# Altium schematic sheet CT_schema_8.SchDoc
size 370 x 335 mm
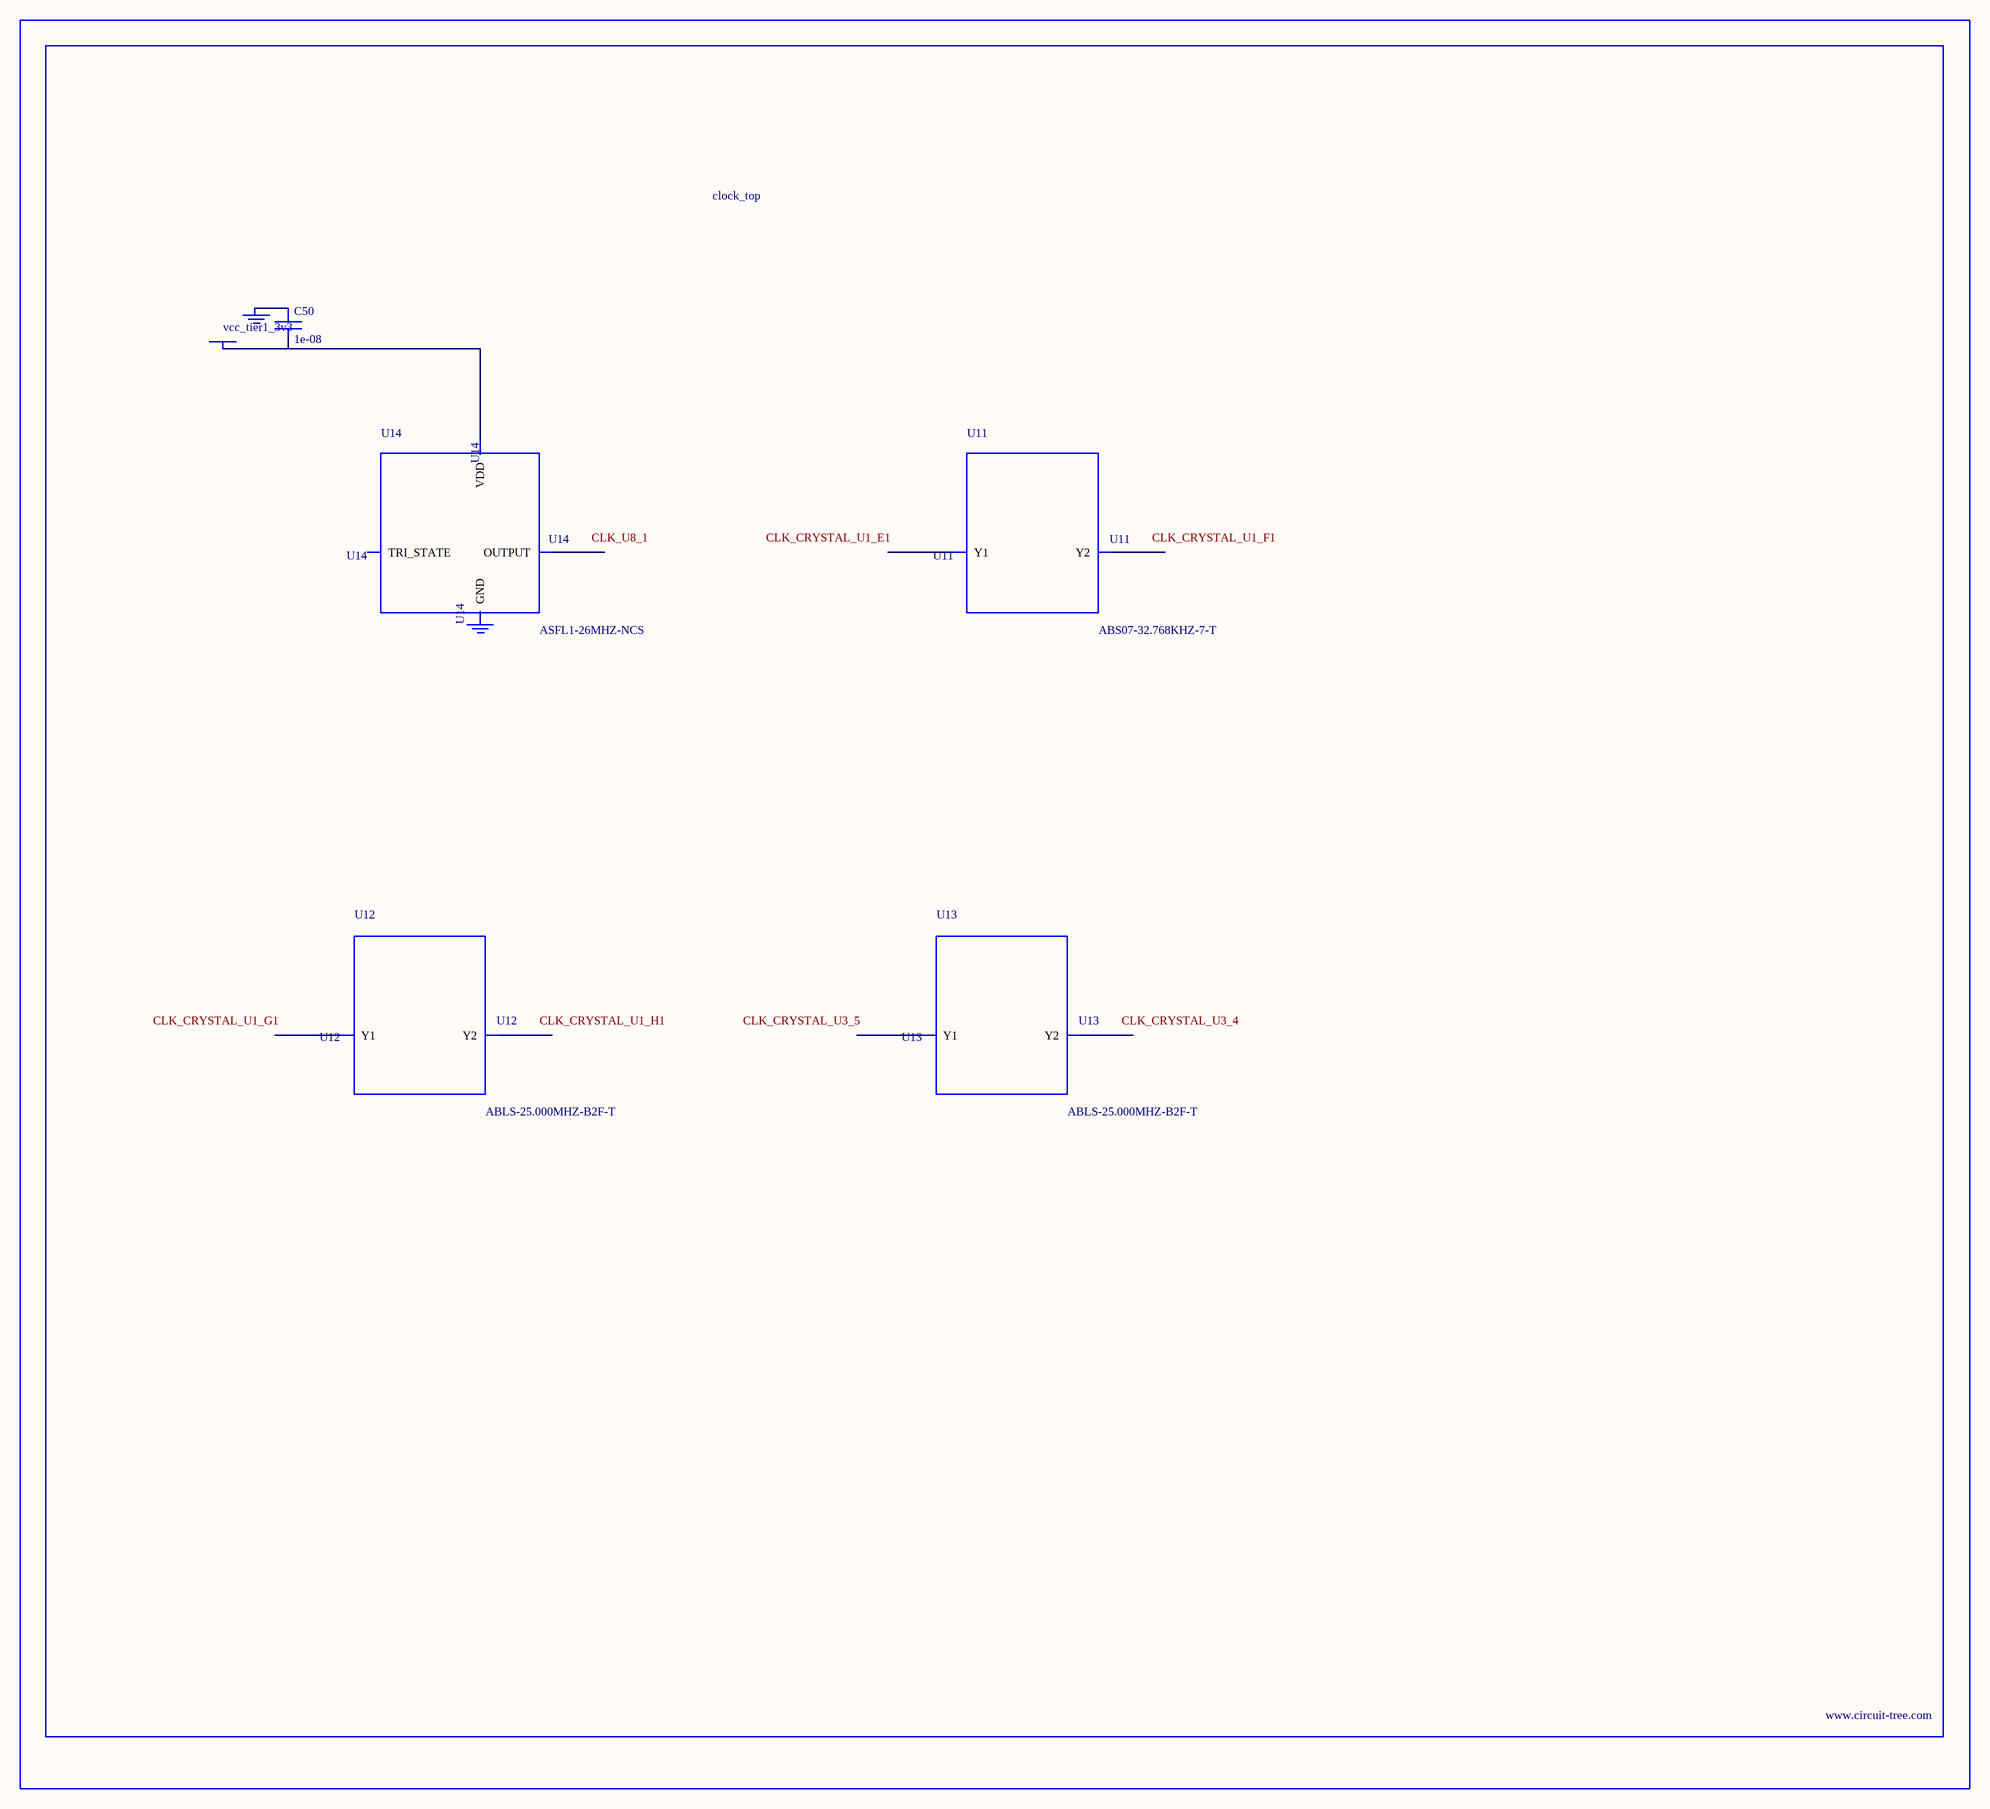
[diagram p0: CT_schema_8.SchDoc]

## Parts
BORDER7  (no value)
C50  1e-08  [C0402]
GND_INSTANCE_7_0  (no value)
GND_INSTANCE_7_1  (no value)
POWER_INSTANCE_7_0  vcc_tier1_3v3
U11  ABS07-32.768KHZ-7-T  [ABS07-32.768KHZ-7-T]
U12  ABLS-25.000MHZ-B2F-T  [ABLS-25.000MHZ-B2F-T]
U13  ABLS-25.000MHZ-B2F-T  [ABLS-25.000MHZ-B2F-T]
U14  ASFL1-26MHZ-NCS  [ASFL1]

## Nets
NetC50_1: C50.1 GND_INSTANCE_7_0.0(GND)
NetC50_2: C50.2 POWER_INSTANCE_7_0.0(PWR) U14.4(VDD)

Not connected (* = marked no-connect by the designer): GND_INSTANCE_7_1 0(GND); U11 1(Y1) 2(Y2); U12 1(Y1) 2(Y2); U13 1(Y1) 2(Y2); U14 1(TRI_STATE) 2(GND) 3(OUTPUT)

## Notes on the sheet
- Labels drawn without touching a wire or pin: CLK_CRYSTAL_U1_E1, CLK_CRYSTAL_U1_F1, CLK_CRYSTAL_U1_G1, CLK_CRYSTAL_U1_H1, CLK_CRYSTAL_U3_4, CLK_CRYSTAL_U3_5, CLK_U8_1

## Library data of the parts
BORDER7 = BORDER_PAGE7
C50 = C0402C103K3RAC
GND_INSTANCE_7_0 GND_INSTANCE_7_1 = GND
POWER_INSTANCE_7_0 = PWR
